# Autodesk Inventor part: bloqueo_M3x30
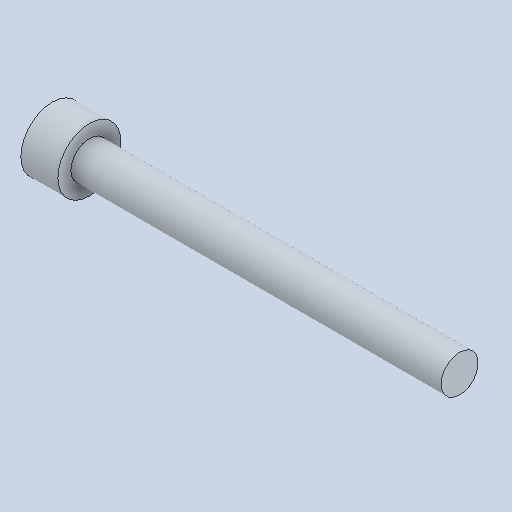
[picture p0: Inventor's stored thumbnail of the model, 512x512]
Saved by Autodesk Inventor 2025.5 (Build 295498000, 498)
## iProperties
Created: 2026-10
Part Number: bloqueo_M3x30
Material: Genérico
Document SubType Name: Modeling
Designer: Luis M
Density: 1 g/cm^3
Appearance: Valor por defecto
Author: Luis M
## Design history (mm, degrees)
feature "Base1"
node "Sólido1"
